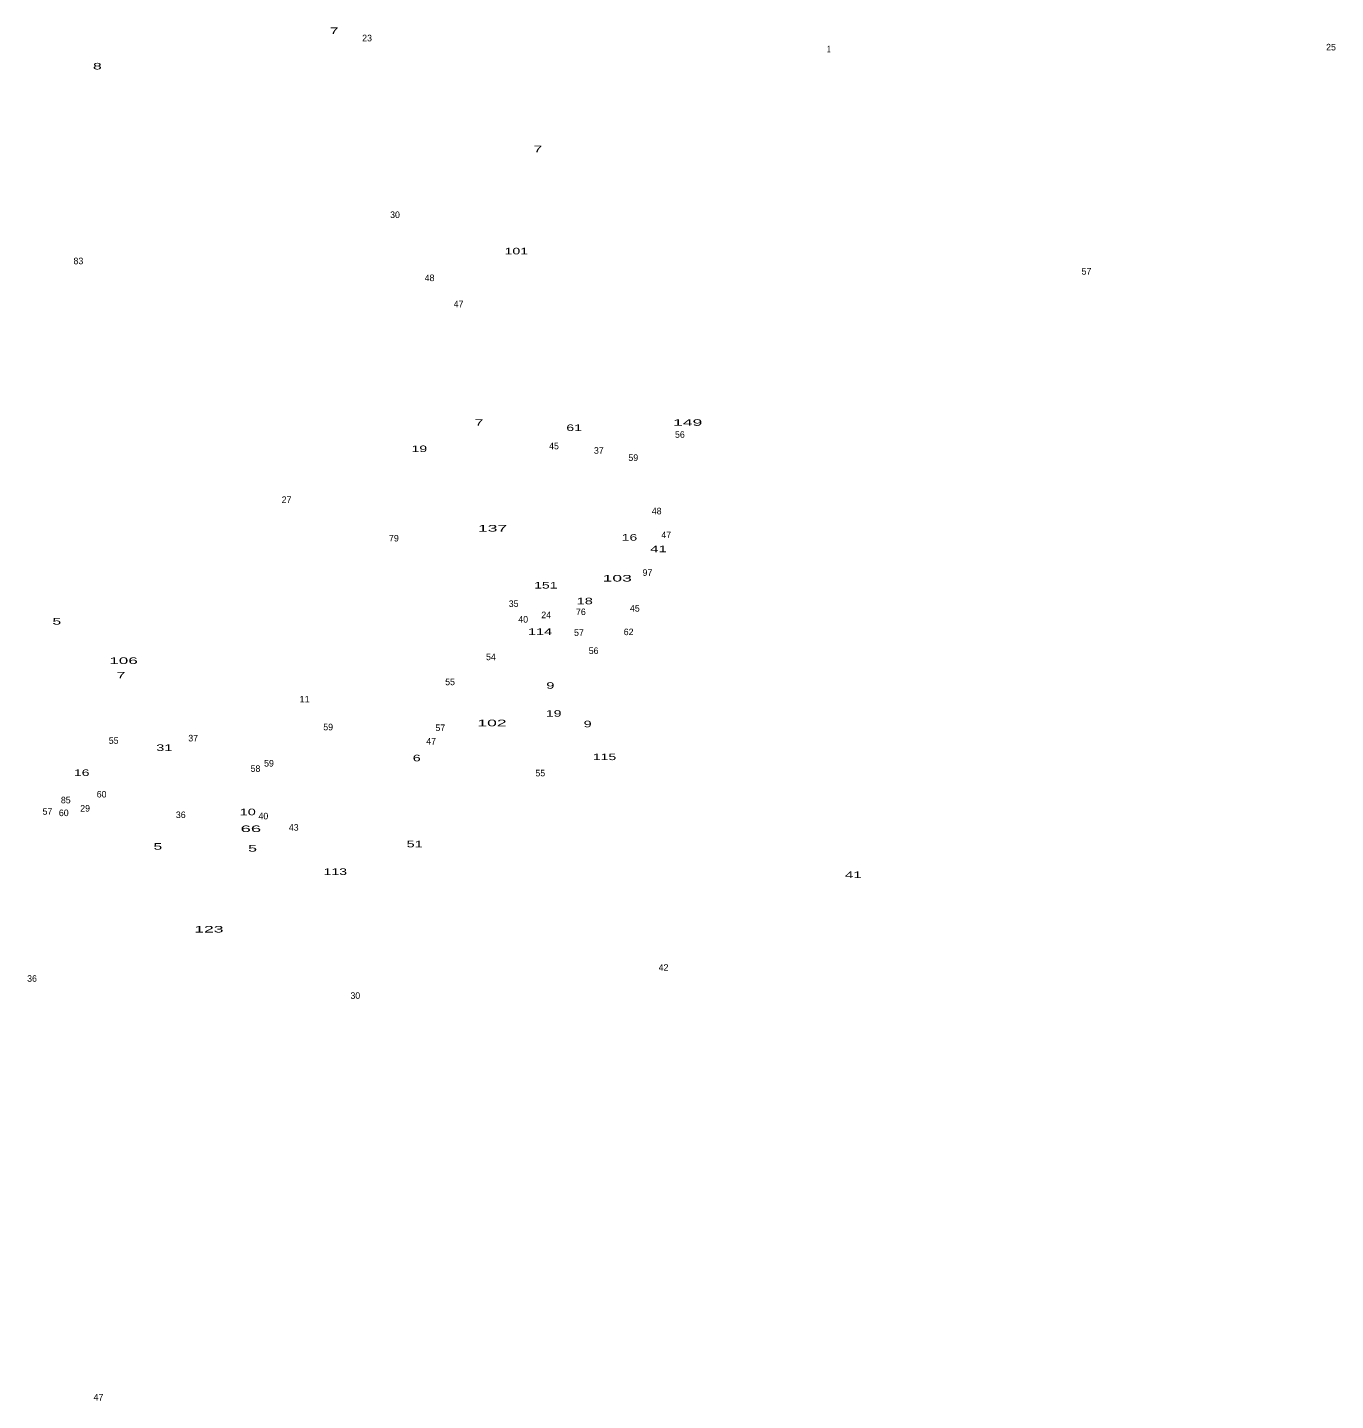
# Model space of a CAD drawing. Extents: x -672598 to -670555, y -997633 to -995506.
# Drawn here: x -671352 to -670555, y -997411 to -996574 of the extents above; entities that cross this region are included whole.
import ezdxf
from ezdxf.enums import TextEntityAlignment as Align

# ---------------------------------------------------------------- set-up
doc = ezdxf.new("R2010")
doc.units = 0
doc.header["$LTSCALE"] = 1.6
doc.layers.add('24', color=7, linetype='Continuous')

msp = doc.modelspace()

# ---------------------------------------------------------------- texts
at = {"layer": '24'}
for s, width, p in [('7', 1.8, (-671165.316, -996578.32)), ('1', 0.65, (-670863.887, -996589.45)), ('8', 1.8, (-671309.641, -996599.93)), ('7', 1.8, (-671041.186, -996650.38)), ('101', 1.6, (-671054.32, -996712.64)), ('7', 1.8, (-671077.036, -996817.14)), ('61', 1.6, (-671019.093, -996820.31)), ('149', 2, (-670949.918, -996817.15)), ('19', 1.6, (-671113.403, -996833.15)), ('137', 2, (-671068.803, -996881.61)), ('16', 1.6, (-670985.383, -996887.16)), ('41', 1.7, (-670967.683, -996894.19)), ('103', 2, (-670992.844, -996912.06)), ('151', 1.6, (-671036.344, -996916.34)), ('18', 1.65, (-671012.607, -996925.94)), ('5', 1.8, (-671334.311, -996938.34)), ('114', 1.65, (-671039.889, -996944.59)), ('106', 1.95, (-671293.659, -996962.31)), ('7', 1.8, (-671295.176, -996971.12)), ('9', 1.65, (-671033.566, -996977.43)), ('11', 1.05, (-671183.314, -996985.78)), ('19', 1.6, (-671031.553, -996994.49)), ('102', 2, (-671069.154, -997000.29)), ('9', 1.65, (-671010.866, -997000.9)), ('31', 1.65, (-671268.847, -997015.35)), ('6', 1.65, (-671115.006, -997021.64)), ('115', 1.6, (-671000.584, -997020.94)), ('16', 1.6, (-671319.183, -997030.59)), ('10', 1.65, (-671217.974, -997054.53)), ('66', 2.1, (-671216.081, -997064.78)), ('5', 1.8, (-671272.761, -997075.54)), ('5', 1.8, (-671215.051, -997076.73)), ('51', 1.65, (-671116.277, -997074.1)), ('113', 1.6, (-671164.614, -997090.9)), ('41', 1.7, (-670848.933, -997092.79)), ('123', 2, (-671241.667, -997126.02))]:
    msp.add_text(s, height=4, dxfattribs=dict(at, width=width)).set_placement(p, align=Align.CENTER)
for s, p in [('23', (-671145.267, -996582.78)), ('25', (-670557.877, -996588.32)), ('30', (-671128.231, -996690.49)), ('83', (-671321.177, -996718.65)), ('57', (-670706.903, -996725.01)), ('48', (-671107.171, -996728.95)), ('47', (-671089.497, -996744.88)), ('56', (-670954.653, -996824.45)), ('45', (-671031.361, -996831.45)), ('37', (-671004.053, -996834.17)), ('59', (-670983.053, -996838.55)), ('27', (-671194.313, -996864.17)), ('48', (-670968.791, -996871.1)), ('79', (-671128.918, -996887.65)), ('47', (-670962.957, -996885.6)), ('97', (-670974.418, -996908.61)), ('35', (-671055.947, -996927.58)), ('40', (-671050.145, -996937.11)), ('24', (-671036.121, -996934.42)), ('76', (-671014.968, -996932.52)), ('45', (-670982.101, -996930.42)), ('57', (-671016.153, -996945.2)), ('62', (-670985.903, -996944.76)), ('54', (-671069.791, -996960.02)), ('56', (-671007.223, -996956.25)), ('55', (-671094.697, -996975.26)), ('59', (-671168.973, -997002.76)), ('57', (-671100.643, -997003.21)), ('55', (-671299.677, -997011.01)), ('37', (-671251.223, -997009.54)), ('47', (-671106.217, -997011.44)), ('58', (-671213.247, -997028.11)), ('59', (-671205.033, -997024.86)), ('55', (-671039.717, -997030.83)), ('60', (-671307.017, -997043.71)), ('57', (-671340.063, -997054.24)), ('60', (-671330.097, -997055.08)), ('85', (-671328.857, -997047.28)), ('29', (-671317.073, -997052.31)), ('36', (-671258.793, -997056.27)), ('40', (-671208.455, -997057.04)), ('43', (-671189.961, -997063.97)), ('42', (-670964.601, -997149.34)), ('36', (-671349.433, -997156.04)), ('30', (-671152.431, -997166.49)), ('47', (-671308.927, -997411.32))]:
    msp.add_text(s, height=4, dxfattribs=at).set_placement(p, align=Align.CENTER)

doc.saveas('drawing.dxf')
